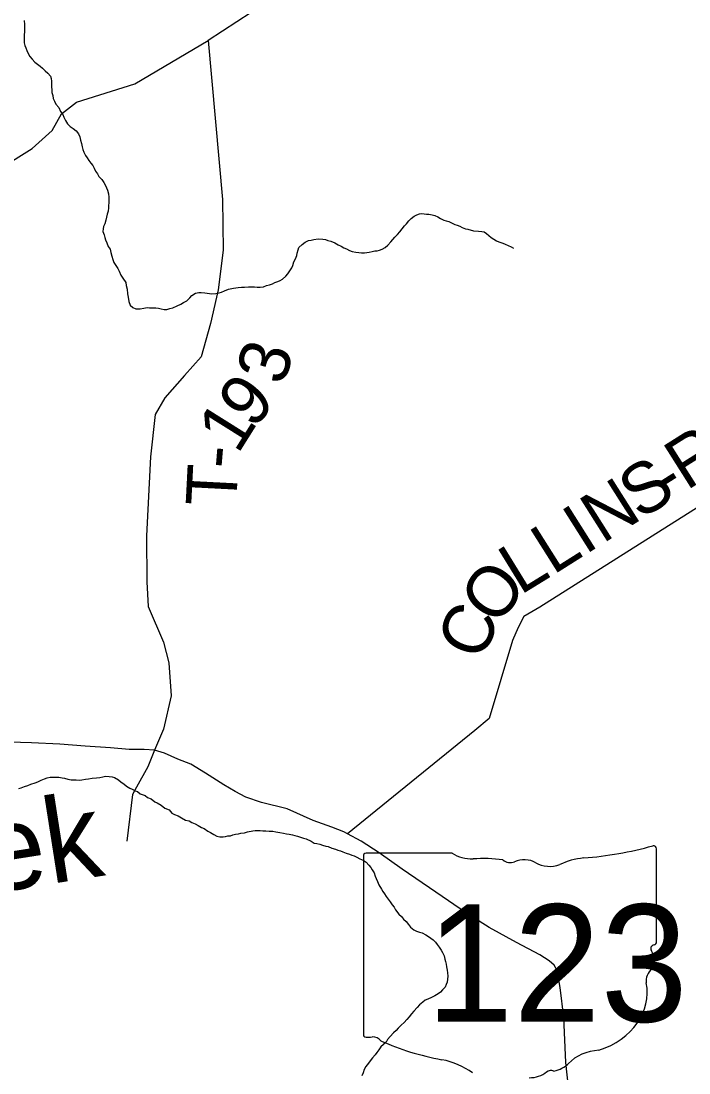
# Model space of a CAD drawing. Extents: x 1310247 to 1664935, y 284496 to 704931.
# Drawn here: x 1536534 to 1540499, y 478494 to 484741 of the extents above; entities that cross this region are included whole.
import ezdxf

# ---------------------------------------------------------------- set-up
doc = ezdxf.new("R2010")
doc.units = 0
for name, color, linetype in [('GM_X_Airport_Class_2', 7, 'Continuous'), ('GM_X_County_Subdivision_Text', 7, 'Continuous'), ('GM_X_Interstate_Shield', 7, 'Continuous'), ('GM_X_Minor_Lake_Text', 7, 'Continuous'), ('GM_X_Minor_River_Text', 7, 'Continuous'), ('GM_X_Township_Subdivision', 7, 'Continuous'), ('GM_X_Unincorporated_Location', 7, 'Continuous')]:
    doc.layers.add(name, color=color, linetype=linetype)

msp = doc.modelspace()

# ---------------------------------------------------------------- linework, layer by layer
at = {"layer": 'GM_X_Airport_Class_2'}
for p, q in [((1538566.2, 479780.6), (1538566.2, 478724)), ((1539092.9, 479798.8), (1538583.3, 479798.8)), ((1540306.4, 479272.3), (1540306.4, 479825)), ((1540306.2, 479272.4), (1540306.4, 479272.3))]:
    msp.add_line(p, q, dxfattribs=at)
for centre, major_axis, start_param, end_param in [((1539686.5, 481239.4), (1845.5, 0), 4.814394, 5.042369), ((1540287.1, 479827.3), (19.4, 0), 6.141152, 7.989035), ((1538586.1, 479782.9), (20.2, 0), 1.712693, 3.28349), ((1539214.3, 479921.5), (195.5, 0), 4.042523, 4.731795), ((1539279.1, 479205.6), (702, 0), 1.404758, 1.657858), ((1539921.9, 479476.1), (371.3, 0), 1.699011, 2.107814), ((1539438.5, 479788.4), (56.4, 0), 3.836095, 5.185415), ((1539521.3, 479666.2), (117.3, 0), 0.950623, 2.079405), ((1539672.7, 479833.7), (141.1, 0), 4.081561, 5.145723), ((1540285.7, 479270.1), (20.7, 0), 5.05454, 6.418171), ((1540301.9, 479231.7), (30, 0), 1.883978, 3.671073), ((1540111.2, 479161.8), (180, 0), 5.934695, 6.695948), ((1540375.8, 479040.9), (130.9, 0), 2.387724, 3.262537), ((1539789.9, 478970.6), (461.6, 0), 5.101752, 6.440018), ((1538586.3, 478721.7), (20.3, 0), 3.00124, 4.508301), ((1538589.4, 478829.8), (155.2, 0), 4.665946, 4.897461), ((1538621.1, 478663), (56, 0), 0.519207, 1.627899), ((1539327.7, 479612.4), (1332.7, 0), 4.195997, 4.488961), ((1539984.5, 478427.3), (252.8, 0), 1.647645, 2.488434), ((1538930.4, 478249.3), (417, 0), 0.823519, 1.323587), ((1539664.2, 478621.6), (149.1, 0), 4.937069, 5.64225), ((1539553.6, 478578.7), (141, 0), 4.691044, 5.507374), ((1539681.1, 478476.3), (39.7, 0), 1.147584, 2.315152)]:
    msp.add_ellipse(centre, major_axis=major_axis, ratio=0.8, start_param=start_param, end_param=end_param, dxfattribs=at)
at = {"layer": 'GM_X_County_Subdivision_Text'}
for points in [[(1538070.2, 484905.2), (1537644, 484625), (1537729.7, 483681.1), (1537733.1, 483380.2), (1537703.3, 483144), (1537658, 482944.2), (1537602.7, 482746.5), (1537504.6, 482635.7), (1537388.1, 482503.2), (1537330.3, 482403.8), (1537302.3, 482153.5), (1537278.9, 481684.6), (1537280.7, 481409.8), (1537288.5, 481263.3), (1537379.6, 481053.3), (1537411.9, 480930.4), (1537424.9, 480733.7), (1537379.6, 480535.8), (1537326.9, 480410.6), (1537285.8, 480312.7), (1537218.9, 480191.3), (1537194.8, 480147.6), (1537162.4, 479871.3)], [(1534215.7, 482805.9), (1535511.9, 483398.7), (1535955.2, 483618.4), (1536419.1, 483871.9), (1536599.6, 483983.4), (1536717.8, 484091.9), (1536773.5, 484189.3), (1536863, 484260.1), (1537210.2, 484369), (1537644, 484625)], [(1543790.2, 482941.4), (1543661.7, 482943.3), (1543395.9, 483025.6), (1543190.4, 483117), (1542991.4, 483234.4), (1542905.7, 483281.9), (1542776.8, 483259.8), (1539614.4, 481259.2), (1539519.1, 481204.6), (1539486, 481138.9), (1539450.7, 481063.2), (1539312.9, 480598.1), (1539227.4, 480527.2), (1538471.1, 479914.1)]]:
    msp.add_lwpolyline(points, dxfattribs=at)
at = {"layer": 'GM_X_Interstate_Shield'}
msp.add_lwpolyline([(1539794.6, 478317.6), (1539769.1, 478555.2), (1539756.5, 478822.6), (1539735.4, 479001.8), (1539716.1, 479102.7), (1539698.8, 479133.3), (1539669.4, 479160.2), (1539614, 479195.9), (1539475, 479268.1), (1539312.4, 479357), (1539177.9, 479443), (1538996.1, 479568.6), (1538796.5, 479704.7), (1538660.3, 479800.9), (1538553.5, 479870.1), (1538471.1, 479914.1), (1538450.3, 479925.2), (1538378.6, 479953.3), (1538268.9, 479992.5), (1538113.8, 480063.1), (1537961.8, 480099.5), (1537868.1, 480132.3), (1537804.6, 480166.2), (1537737.2, 480204.2), (1537628.4, 480273.5), (1537541.2, 480328.2), (1537465.6, 480358.4), (1537386, 480392.7), (1537326.9, 480410.6), (1537265.8, 480414.2), (1537175.1, 480414.8), (1537064.6, 480423.9), (1536913.9, 480434.1), (1536763.2, 480446.4), (1536596.3, 480455.1), (1536465.4, 480458.8)], dxfattribs=at)
at = {"layer": 'GM_X_Minor_River_Text'}
for points in [[(1536552.2, 484744.1), (1536553.6, 484720), (1536555.2, 484705.9), (1536554.6, 484681.8), (1536552, 484655.8), (1536551.5, 484637.8), (1536552.9, 484611.6), (1536556.5, 484595.5), (1536562.2, 484581.3), (1536567.8, 484565.1), (1536575.4, 484548.9), (1536587, 484530.5), (1536600.7, 484514.2), (1536616.4, 484497.7), (1536632.1, 484485.3), (1536647.9, 484472.9), (1536661.6, 484460.5), (1536677.3, 484446.1), (1536693.1, 484431.7), (1536708.7, 484413.2), (1536712.3, 484399.1), (1536713.9, 484383), (1536715.6, 484366.9), (1536715.1, 484348.9), (1536716.8, 484334.8), (1536716.3, 484316.8), (1536721.9, 484298.6), (1536725.5, 484280.4), (1536733.1, 484264.2), (1536740.7, 484247.9), (1536758.3, 484227.5), (1536767.7, 484203.1), (1536781.4, 484186.8), (1536787, 484170.6), (1536798.6, 484150.2), (1536810.1, 484129.9), (1536825.8, 484115.5), (1536843.6, 484103), (1536861.3, 484088.5), (1536875, 484072.1), (1536882.5, 484053.9), (1536886.1, 484033.8), (1536893.6, 484013.5), (1536897.1, 483993.4), (1536900.7, 483977.2), (1536906.4, 483963), (1536915.9, 483942.8), (1536925.6, 483928.5)], [(1536925.6, 483928.5), (1536937.3, 483912.1), (1536949, 483897.8), (1536960.7, 483883.5), (1536968.3, 483867.2), (1536975.9, 483849), (1536987.5, 483832.7), (1536995.2, 483818.4), (1537012.8, 483800), (1537024.4, 483781.6), (1537034.1, 483767.3), (1537041.7, 483751.1), (1537047.4, 483736.9), (1537052.9, 483714.7), (1537054.4, 483694.6), (1537056, 483676.5), (1537055.6, 483660.5), (1537053.2, 483646.5), (1537052.9, 483632.5), (1537050.4, 483612.5), (1537045.9, 483594.5), (1537041.4, 483576.5), (1537037, 483558.6), (1537030.4, 483536.7), (1537024, 483520.8), (1537021.6, 483506.8), (1537019.2, 483490.8), (1537026.7, 483470.6), (1537030.4, 483456.4), (1537036.1, 483442.2), (1537043.7, 483424), (1537051.2, 483401.8), (1537062.8, 483385.4), (1537066.4, 483367.3), (1537073.8, 483345), (1537079.4, 483324.8), (1537085, 483306.6), (1537096.5, 483288.3), (1537108.2, 483272), (1537115.8, 483255.7), (1537127.3, 483231.4), (1537138.9, 483213), (1537156.3, 483188.5), (1537157.9, 483170.4), (1537163.4, 483148.2), (1537166.7, 483120.1), (1537170.3, 483101.9), (1537173.6, 483075.8), (1537181.1, 483053.5), (1537196.8, 483039.1), (1537214.8, 483032.6), (1537240.8, 483032), (1537263, 483035.5), (1537283.2, 483039), (1537297.3, 483038.7), (1537311.3, 483038.3), (1537333.4, 483037.8), (1537349.4, 483035.4), (1537365.4, 483031), (1537383.4, 483028.6), (1537399.5, 483028.2), (1537417.7, 483033.8), (1537435.8, 483037.3), (1537460.2, 483048.8), (1537482.6, 483060.3), (1537498.9, 483069.9), (1537517.2, 483079.5), (1537535.8, 483097.1), (1537548.2, 483110.9), (1537570.6, 483124.4), (1537588.8, 483127.9), (1537602.9, 483129.6), (1537624.9, 483127.1), (1537638.9, 483124.7), (1537652.9, 483122.4), (1537666.9, 483120), (1537691.1, 483123.5), (1537709.3, 483127), (1537723.4, 483130.7), (1537741.7, 483138.3), (1537766, 483147.7), (1537794.3, 483155.1), (1537822.5, 483158.4), (1537842.7, 483159.9), (1537860.8, 483161.5), (1537884.9, 483162.9), (1537899, 483162.6), (1537919.1, 483162.1), (1537935.1, 483159.7), (1537953.2, 483161.3), (1537973.3, 483162.8), (1537991.6, 483170.4), (1538009.8, 483174), (1538026, 483179.6), (1538040.2, 483187.3), (1538058.5, 483194.9), (1538072.7, 483200.5), (1538086.9, 483208.2), (1538105.5, 483225.8), (1538117.8, 483239.6), (1538130.3, 483257.3)], [(1538130.3, 483257.3), (1538140.8, 483275.1), (1538147.2, 483289), (1538153.8, 483311), (1538164.3, 483328.8), (1538170.8, 483348.7), (1538173.1, 483362.6), (1538179.7, 483382.6), (1538184, 483396.5), (1538202.5, 483414.1), (1538221, 483427.7), (1538241.3, 483437.2), (1538255.4, 483438.9), (1538271.6, 483444.5), (1538297.8, 483447.9), (1538325.9, 483445.2), (1538341.9, 483442.8), (1538355.8, 483438.5), (1538373.8, 483434.1), (1538397.6, 483423.5), (1538417.5, 483412.9), (1538435.3, 483404.5), (1538451.1, 483394.1), (1538467.1, 483387.7), (1538484.9, 483379.2), (1538498.8, 483372.8), (1538520.8, 483368.3), (1538538.8, 483365.9), (1538554.8, 483363.5), (1538573, 483365), (1538587.1, 483366.7), (1538601.2, 483368.4), (1538619.3, 483372), (1538633.5, 483375.6), (1538647.6, 483377.3), (1538661.7, 483381), (1538678, 483386.6), (1538696.3, 483396.2), (1538710.7, 483409.9), (1538729.2, 483429.5), (1538741.6, 483443.2), (1538754, 483457), (1538768.5, 483472.7), (1538782.9, 483488.4), (1538797.4, 483506.1), (1538809.9, 483523.9), (1538822.3, 483537.6), (1538836.8, 483555.3), (1538849.2, 483569.1), (1538867.6, 483582.7), (1538883.9, 483590.3), (1538900.1, 483595.9), (1538914.2, 483597.6), (1538940.3, 483595), (1538954.3, 483594.6), (1538974.3, 483590.1), (1538990.3, 483585.7), (1539008.1, 483577.3), (1539024, 483568.9), (1539043.8, 483558.3), (1539057.8, 483554), (1539073.7, 483549.6), (1539089.6, 483543.2), (1539109.5, 483532.7), (1539123.4, 483528.3), (1539139.3, 483521.9), (1539153.2, 483515.6), (1539173.1, 483507.1), (1539187.1, 483504.7), (1539221.1, 483495.9), (1539249.1, 483493.2), (1539269.1, 483490.7), (1539283.1, 483488.4), (1539297, 483480), (1539310.8, 483467.6), (1539324.5, 483455.3), (1539340.3, 483444.8), (1539356.2, 483436.4), (1539370.1, 483430.1), (1539394, 483421.5), (1539407.9, 483415.1), (1539425.8, 483408.7), (1539443.7, 483400.2), (1539457.5, 483391.9)], [(1536521.3, 480184.1), (1536535.5, 480187.7), (1536553.7, 480195.3), (1536573.9, 480200.8), (1536592.2, 480208.4), (1536618.6, 480217.8), (1536632.8, 480223.5), (1536653.1, 480233), (1536673.4, 480240.6), (1536689.6, 480246.2), (1536707.7, 480249.8), (1536723.9, 480251.4), (1536743.9, 480250.9), (1536758, 480250.6), (1536778, 480246.1), (1536792, 480243.7), (1536811.9, 480239.2), (1536831.9, 480234.8), (1536846, 480234.4), (1536862, 480234), (1536880.1, 480233.6), (1536894.2, 480235.3), (1536916.4, 480238.7), (1536934.5, 480240.3), (1536956.7, 480243.8), (1536980.9, 480247.2), (1537001, 480248.7), (1537019.2, 480252.3), (1537035.4, 480255.9), (1537057.4, 480255.4), (1537075.5, 480253), (1537089.4, 480248.6), (1537113.2, 480234), (1537128.9, 480221.6), (1537144.7, 480211.2), (1537160.5, 480196.7), (1537180.3, 480186.2), (1537194.2, 480179.9), (1537212, 480169.4), (1537226, 480165), (1537241.7, 480152.6), (1537271.6, 480141.9), (1537285.3, 480129.5), (1537307.2, 480121), (1537328.9, 480104.4), (1537342.8, 480098), (1537366.6, 480083.4), (1537388.2, 480066.8), (1537414.1, 480056.2), (1537429.7, 480037.7), (1537445.6, 480029.3), (1537467.5, 480020.8), (1537487.2, 480008.2), (1537511, 479995.6), (1537533, 479991.1), (1537548.8, 479980.7), (1537566.8, 479974.2), (1537584.6, 479963.8), (1537604.3, 479951.2), (1537620.3, 479944.8), (1537642, 479930.3), (1537657.9, 479921.9), (1537677.6, 479909.4), (1537695.5, 479900.9), (1537713.5, 479896.5), (1537733.6, 479896), (1537747.7, 479897.6), (1537761.8, 479901.3), (1537777.9, 479902.9), (1537792.1, 479908.6), (1537806.3, 479912.3), (1537824.4, 479913.8), (1537838.5, 479917.5), (1537860.7, 479921)], [(1537860.7, 479921), (1537879, 479926.6), (1537909.2, 479931.9), (1537923.3, 479933.5), (1537937.4, 479933.2), (1537953.5, 479934.8), (1537969.5, 479932.4), (1537987.6, 479932), (1538007.6, 479929.5), (1538029.7, 479929), (1538045.7, 479926.6), (1538069.7, 479922), (1538091.7, 479917.4), (1538109.7, 479915), (1538125.7, 479912.6), (1538145.7, 479908.1), (1538159.6, 479903.8), (1538175.6, 479899.3), (1538193.6, 479894.9), (1538211.5, 479888.4), (1538227.4, 479884), (1538257.3, 479871.3), (1538275, 479858.8), (1538289, 479856.5), (1538307, 479852), (1538323, 479847.6), (1538342.9, 479841.1), (1538356.9, 479838.8), (1538378.7, 479828.2), (1538400.7, 479823.7), (1538414.6, 479817.3), (1538430.6, 479812.9), (1538444.5, 479806.6), (1538464.4, 479800.1), (1538484.3, 479793.6), (1538498.3, 479787.2), (1538512.2, 479782.9), (1538528.1, 479776.5), (1538545.9, 479766), (1538565.8, 479757.5), (1538583.6, 479745), (1538599.3, 479728.6), (1538610.9, 479714.3), (1538618.6, 479700), (1538630.2, 479681.7), (1538635.8, 479663.5), (1538641.5, 479649.3), (1538651.1, 479631), (1538658.6, 479610.8), (1538674.1, 479586.3), (1538681.8, 479572.1), (1538691.4, 479557.8), (1538701.1, 479541.5), (1538712.7, 479525.2), (1538724.4, 479510.9), (1538738, 479492.5), (1538749.7, 479478.2), (1538757.4, 479461.9), (1538776.8, 479437.4), (1538792.6, 479423), (1538804.2, 479406.6), (1538820, 479394.2), (1538833.6, 479375.8), (1538845.2, 479359.5), (1538864.9, 479343), (1538880.8, 479336.6), (1538898.7, 479330.1), (1538914.7, 479325.7), (1538936.5, 479315.1), (1538952.3, 479304.7), (1538966.1, 479294.4), (1538979.9, 479284), (1538993.7, 479271.6), (1539005.4, 479257.3), (1539017, 479241), (1539028.6, 479222.6), (1539036.3, 479208.4), (1539045.9, 479190.1), (1539049.4, 479170), (1539053.1, 479155.8), (1539058.7, 479139.6), (1539060.3, 479123.5), (1539063.9, 479105.4), (1539065.5, 479089.3), (1539067, 479069.2), (1539066.6, 479051.2), (1539064.1, 479033.1), (1539057.7, 479019.3), (1539051.3, 479003.4), (1539036.9, 478987.7), (1539024.5, 478973.9), (1539010.2, 478964.2), (1538989.8, 478952.7), (1538971.5, 478943.1), (1538949.1, 478931.6), (1538932.9, 478926), (1538918.5, 478914.3), (1538900.1, 478898.7), (1538885.6, 478883), (1538865, 478861.4), (1538852.5, 478845.6)], [(1538852.5, 478845.6), (1538838, 478827.9), (1538823.6, 478812.2), (1538809.1, 478794.5), (1538790.6, 478776.9), (1538772, 478759.3), (1538761.7, 478745.5), (1538745.2, 478731.8), (1538724.6, 478710.3), (1538710.1, 478692.6), (1538701.7, 478676.7), (1538685.3, 478663.1), (1538670.9, 478649.4), (1538658.4, 478631.6), (1538645.9, 478615.8), (1538635.5, 478602.1), (1538621, 478584.3), (1538606.5, 478566.6), (1538596.2, 478552.8), (1538581.6, 478533.1), (1538571.1, 478515.3), (1538564.6, 478495.4), (1538558.1, 478477.5)]]:
    msp.add_lwpolyline(points, dxfattribs=at)

# ---------------------------------------------------------------- texts
at = {"layer": 'GM_X_Airport_Class_2'}
msp.add_text('123', height=696.1, dxfattribs=at).set_placement((1538939.4, 478798.5))
at = {"layer": 'GM_X_Minor_Lake_Text'}
msp.add_text('Creek', height=499.98, rotation=8.91251, dxfattribs=at).set_placement((1535276.9, 479391.6))
at = {"layer": 'GM_X_Township_Subdivision'}
for s, rotation, p in [('3', 73.67636, (1538093.2, 482570.6)), ('9', 50.16977, (1537912.1, 482311.1)), ('1', 57.90359, (1537820.2, 482163.2)), ('R', 32.30656, (1540484, 481949.3)), ('-', 85.26422, (1537821.9, 482076)), ('T', 87.06739, (1537810.6, 481854.4)), ('S', 32.30355, (1540208.8, 481775.3)), ('N', 32.30579, (1539985.6, 481634.2)), ('-', 32.30561, (1540379.9, 481883.5)), ('I', 32.30561, (1539881.5, 481568.4)), ('L', 32.28633, (1539691.7, 481448.5)), ('L', 31.57746, (1539497.1, 481328.8)), ('O', 51.95632, (1539355.3, 481139.6)), ('C', 66.45956, (1539267.2, 480930.9))]:
    msp.add_text(s, height=300, rotation=rotation, dxfattribs=at).set_placement(p)
at = {"layer": 'GM_X_Unincorporated_Location'}
for s in ['s', 'r']:
    msp.add_text(s, height=1, dxfattribs=at).set_placement((1539416.7, 479182.1))
msp.add_text('123', height=1, rotation=0.00001, dxfattribs=at).set_placement((1539063.7, 479109.3))

doc.saveas('drawing.dxf')
